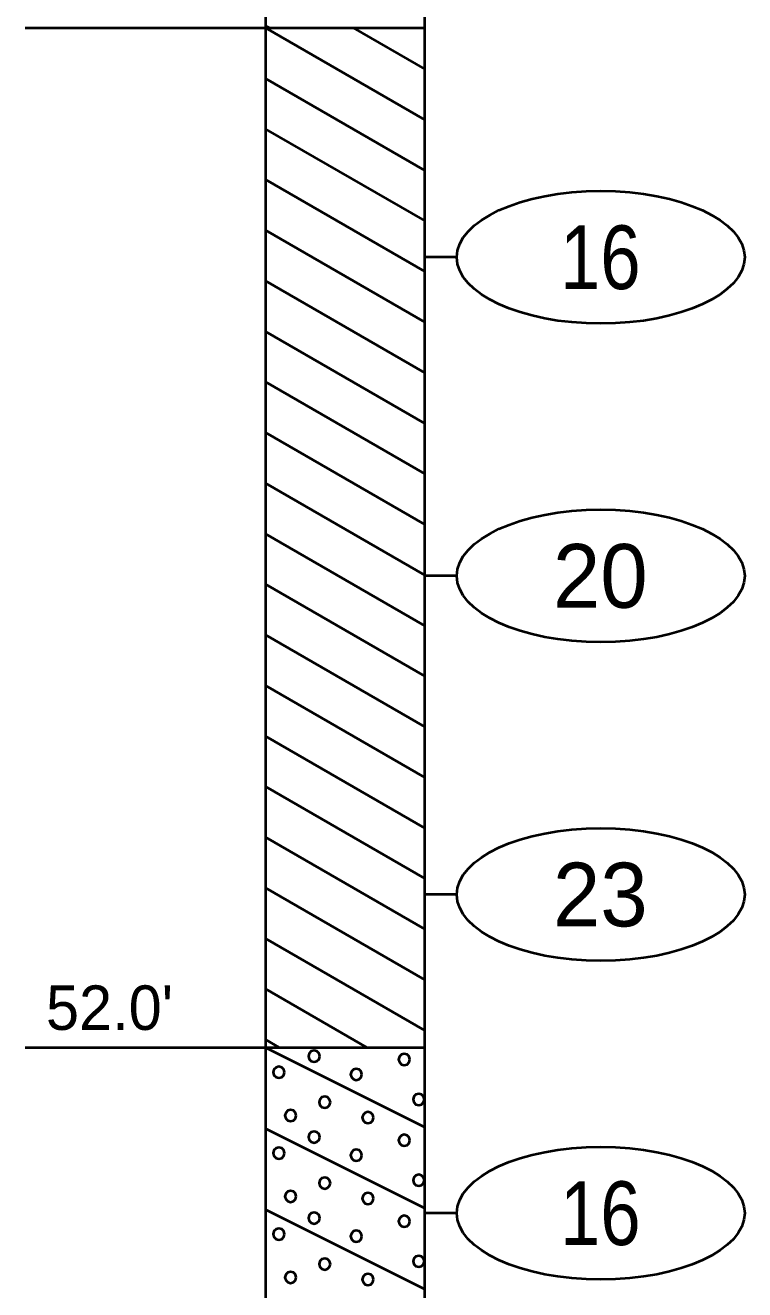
# Model space of a CAD drawing. Extents: x -76 to 974, y -1080 to -735.
# Drawn here: x 37.75 to 49.03, y -820.52 to -800.68 of the extents above; entities that cross this region are included whole.
import ezdxf
from ezdxf.enums import TextEntityAlignment as Align

# ---------------------------------------------------------------- set-up
doc = ezdxf.new("R2010")
doc.units = 0
doc.header["$LTSCALE"] = 0.36
doc.layers.add('27', color=7, linetype='Continuous', lineweight=40)

msp = doc.modelspace()

# ---------------------------------------------------------------- linework, layer by layer
at = {"layer": '27'}
for p, q in [((41.5129, -786.7173), (41.5129, -800.7173)), ((44.0129, -800.7173), (44.0129, -786.7173)), ((37.7455, -800.7173), (41.5129, -800.7173)), ((41.5129, -800.6873), (41.5729, -800.7173)), ((41.5129, -800.7173), (44.0129, -800.7173)), ((41.5129, -800.7173), (44.0129, -802.1607)), ((41.5129, -800.7173), (41.5129, -816.7173)), ((42.8877, -800.7173), (44.0129, -801.3669)), ((42.8877, -800.7173), (44.0129, -801.3669)), ((44.0129, -816.7173), (44.0129, -800.7173)), ((41.5129, -801.511), (44.0129, -802.9544)), ((41.5129, -801.511), (44.0129, -802.9544)), ((41.5129, -802.3048), (44.0129, -803.7482)), ((41.5129, -803.0985), (44.0129, -804.5419)), ((41.5129, -803.0985), (44.0129, -804.5419)), ((41.5129, -803.8923), (44.0129, -805.3357)), ((44.5129, -804.3173), (44.0129, -804.3173)), ((41.5129, -804.686), (44.0129, -806.1294)), ((41.5129, -804.686), (44.0129, -806.1294)), ((41.5129, -805.4798), (44.0129, -806.9232)), ((41.5129, -806.2735), (44.0129, -807.7169)), ((41.5129, -806.2735), (44.0129, -807.7169)), ((41.5129, -807.0673), (44.0129, -808.5107)), ((41.5129, -807.861), (44.0129, -809.3044)), ((41.5129, -807.861), (44.0129, -809.3044)), ((41.5129, -808.6548), (44.0129, -810.0982)), ((41.5129, -809.4485), (44.0129, -810.8919)), ((41.5129, -809.4485), (44.0129, -810.8919)), ((44.5129, -809.3173), (44.0129, -809.3173)), ((41.5129, -810.2423), (44.0129, -811.6857)), ((41.5129, -811.036), (44.0129, -812.4794)), ((41.5129, -811.036), (44.0129, -812.4794)), ((41.5129, -811.8298), (44.0129, -813.2732)), ((41.5129, -812.6235), (44.0129, -814.0669)), ((41.5129, -812.6235), (44.0129, -814.0669)), ((41.5129, -813.4173), (44.0129, -814.8607)), ((41.5129, -814.211), (44.0129, -815.6544)), ((41.5129, -814.211), (44.0129, -815.6544)), ((44.5129, -814.3173), (44.0129, -814.3173)), ((41.5129, -815.0048), (44.0129, -816.4482)), ((41.5129, -815.7985), (43.1042, -816.7173)), ((41.5129, -815.7985), (43.1042, -816.7173)), ((41.5129, -816.5923), (41.7294, -816.7173)), ((37.7455, -816.7173), (41.5129, -816.7173)), ((41.5129, -816.7173), (44.0129, -816.7173)), ((41.5129, -816.7173), (44.0129, -817.9673)), ((41.5129, -816.7173), (41.5129, -821.7173)), ((44.0129, -821.7173), (44.0129, -816.7173)), ((41.5129, -817.9873), (44.0129, -819.2373)), ((41.5129, -819.2573), (44.0129, -820.5073)), ((44.5129, -819.3173), (44.0129, -819.3173))]:
    msp.add_line(p, q, dxfattribs=at)
for points in [[(42.3636, -816.8536), (42.3517, -816.8092), (42.3191, -816.7766), (42.2747, -816.7647), (42.2302, -816.7766), (42.1977, -816.8092), (42.1858, -816.8536), (42.1977, -816.8981), (42.2302, -816.9306), (42.2747, -816.9425), (42.3191, -816.9306), (42.3517, -816.8981)], [(43.7784, -816.9045), (43.7665, -816.8601), (43.734, -816.8275), (43.6895, -816.8156), (43.6451, -816.8275), (43.6126, -816.8601), (43.6006, -816.9045), (43.6126, -816.949), (43.6451, -816.9815), (43.6895, -816.9934), (43.734, -816.9815), (43.7665, -816.949)], [(41.8105, -817.1054), (41.7986, -817.0609), (41.7661, -817.0284), (41.7216, -817.0165), (41.6772, -817.0284), (41.6446, -817.0609), (41.6327, -817.1054), (41.6446, -817.1498), (41.6772, -817.1824), (41.7216, -817.1943), (41.7661, -817.1824), (41.7986, -817.1498)], [(43.0258, -817.1384), (43.0139, -817.094), (42.9814, -817.0615), (42.9369, -817.0495), (42.8925, -817.0615), (42.86, -817.094), (42.848, -817.1384), (42.86, -817.1829), (42.8925, -817.2154), (42.9369, -817.2273), (42.9814, -817.2154), (43.0139, -817.1829)], [(42.5301, -817.5758), (42.5181, -817.5313), (42.4856, -817.4988), (42.4412, -817.4869), (42.3967, -817.4988), (42.3642, -817.5313), (42.3523, -817.5758), (42.3642, -817.6202), (42.3967, -817.6528), (42.4412, -817.6647), (42.4856, -817.6528), (42.5181, -817.6202)], [(44.0047, -817.5325), (43.9928, -817.4881), (43.9603, -817.4555), (43.9158, -817.4436), (43.8714, -817.4555), (43.8388, -817.4881), (43.8269, -817.5325), (43.8388, -817.577), (43.8714, -817.6095), (43.9158, -817.6214), (43.9603, -817.6095), (43.9928, -817.577)], [(41.9948, -817.7843), (41.9829, -817.7398), (41.9504, -817.7073), (41.9059, -817.6954), (41.8615, -817.7073), (41.829, -817.7398), (41.817, -817.7843), (41.829, -817.8287), (41.8615, -817.8612), (41.9059, -817.8732), (41.9504, -817.8612), (41.9829, -817.8287)], [(43.2076, -817.8173), (43.1957, -817.7729), (43.1632, -817.7403), (43.1187, -817.7284), (43.0743, -817.7403), (43.0418, -817.7729), (43.0298, -817.8173), (43.0418, -817.8618), (43.0743, -817.8943), (43.1187, -817.9062), (43.1632, -817.8943), (43.1957, -817.8618)], [(42.3635, -818.1224), (42.3516, -818.078), (42.3191, -818.0454), (42.2746, -818.0335), (42.2302, -818.0454), (42.1976, -818.078), (42.1857, -818.1224), (42.1976, -818.1669), (42.2302, -818.1994), (42.2746, -818.2113), (42.3191, -818.1994), (42.3516, -818.1669)], [(43.7784, -818.1733), (43.7665, -818.1288), (43.734, -818.0963), (43.6895, -818.0844), (43.6451, -818.0963), (43.6126, -818.1288), (43.6006, -818.1733), (43.6126, -818.2177), (43.6451, -818.2502), (43.6895, -818.2622), (43.734, -818.2502), (43.7665, -818.2177)], [(41.8105, -818.3741), (41.7986, -818.3297), (41.7661, -818.2971), (41.7216, -818.2852), (41.6772, -818.2971), (41.6446, -818.3297), (41.6327, -818.3741), (41.6446, -818.4186), (41.6772, -818.4511), (41.7216, -818.463), (41.7661, -818.4511), (41.7986, -818.4186)], [(43.0258, -818.4072), (43.0139, -818.3627), (42.9814, -818.3302), (42.9369, -818.3183), (42.8925, -818.3302), (42.86, -818.3627), (42.848, -818.4072), (42.86, -818.4516), (42.8925, -818.4842), (42.9369, -818.4961), (42.9814, -818.4842), (43.0139, -818.4516)], [(42.5301, -818.8445), (42.5181, -818.8), (42.4856, -818.7675), (42.4412, -818.7556), (42.3967, -818.7675), (42.3642, -818.8), (42.3523, -818.8445), (42.3642, -818.8889), (42.3967, -818.9215), (42.4412, -818.9334), (42.4856, -818.9215), (42.5181, -818.8889)], [(44.0047, -818.8013), (43.9928, -818.7568), (43.9603, -818.7243), (43.9158, -818.7124), (43.8714, -818.7243), (43.8388, -818.7568), (43.8269, -818.8013), (43.8388, -818.8457), (43.8714, -818.8783), (43.9158, -818.8902), (43.9603, -818.8783), (43.9928, -818.8457)], [(41.9948, -819.053), (41.9829, -819.0085), (41.9504, -818.976), (41.9059, -818.9641), (41.8615, -818.976), (41.829, -819.0085), (41.817, -819.053), (41.829, -819.0974), (41.8615, -819.13), (41.9059, -819.1419), (41.9504, -819.13), (41.9829, -819.0974)], [(43.2076, -819.086), (43.1957, -819.0416), (43.1632, -819.009), (43.1187, -818.9971), (43.0743, -819.009), (43.0418, -819.0416), (43.0298, -819.086), (43.0418, -819.1305), (43.0743, -819.163), (43.1187, -819.1749), (43.1632, -819.163), (43.1957, -819.1305)], [(42.3636, -819.3936), (42.3517, -819.3492), (42.3191, -819.3166), (42.2747, -819.3047), (42.2302, -819.3166), (42.1977, -819.3492), (42.1858, -819.3936), (42.1977, -819.4381), (42.2302, -819.4706), (42.2747, -819.4825), (42.3191, -819.4706), (42.3517, -819.4381)], [(43.7784, -819.4445), (43.7665, -819.4001), (43.734, -819.3675), (43.6895, -819.3556), (43.6451, -819.3675), (43.6126, -819.4001), (43.6006, -819.4445), (43.6126, -819.489), (43.6451, -819.5215), (43.6895, -819.5334), (43.734, -819.5215), (43.7665, -819.489)], [(41.8105, -819.6454), (41.7986, -819.6009), (41.7661, -819.5684), (41.7216, -819.5565), (41.6772, -819.5684), (41.6446, -819.6009), (41.6327, -819.6454), (41.6446, -819.6898), (41.6772, -819.7224), (41.7216, -819.7343), (41.7661, -819.7224), (41.7986, -819.6898)], [(43.0258, -819.6784), (43.0139, -819.634), (42.9814, -819.6015), (42.9369, -819.5895), (42.8925, -819.6015), (42.86, -819.634), (42.848, -819.6784), (42.86, -819.7229), (42.8925, -819.7554), (42.9369, -819.7673), (42.9814, -819.7554), (43.0139, -819.7229)], [(44.0047, -820.0725), (43.9928, -820.0281), (43.9603, -819.9955), (43.9158, -819.9836), (43.8714, -819.9955), (43.8388, -820.0281), (43.8269, -820.0725), (43.8388, -820.117), (43.8714, -820.1495), (43.9158, -820.1614), (43.9603, -820.1495), (43.9928, -820.117)], [(42.5301, -820.1158), (42.5181, -820.0713), (42.4856, -820.0388), (42.4412, -820.0269), (42.3967, -820.0388), (42.3642, -820.0713), (42.3523, -820.1158), (42.3642, -820.1602), (42.3967, -820.1928), (42.4412, -820.2047), (42.4856, -820.1928), (42.5181, -820.1602)], [(41.9948, -820.3243), (41.9829, -820.2798), (41.9504, -820.2473), (41.9059, -820.2354), (41.8615, -820.2473), (41.829, -820.2798), (41.817, -820.3243), (41.829, -820.3687), (41.8615, -820.4012), (41.9059, -820.4132), (41.9504, -820.4012), (41.9829, -820.3687)], [(43.2076, -820.3573), (43.1957, -820.3129), (43.1632, -820.2803), (43.1187, -820.2684), (43.0743, -820.2803), (43.0418, -820.3129), (43.0298, -820.3573), (43.0418, -820.4018), (43.0743, -820.4343), (43.1187, -820.4462), (43.1632, -820.4343), (43.1957, -820.4018)]]:
    msp.add_lwpolyline(points, close=True, dxfattribs=at)
for centre in [(46.7703, -804.3173), (46.7703, -809.3173), (46.7703, -814.3173), (46.7703, -819.3173)]:
    msp.add_ellipse(centre, major_axis=(2.2574, 0), ratio=0.461538, dxfattribs=at)

# ---------------------------------------------------------------- texts
at = {"layer": '27', "width": 0.85}
for p in [(46.7631, -804.8172), (46.7631, -819.8172)]:
    msp.add_text('16', height=1, dxfattribs=at).set_placement(p, align=Align.CENTER)
at = {"layer": '27'}
for s, p in [('20', (46.7632, -809.8172)), ('23', (46.7632, -814.8172))]:
    msp.add_text(s, height=1, dxfattribs=at).set_placement(p, align=Align.CENTER)
msp.add_text("52.0'", height=0.6976, dxfattribs=at).set_placement((38.0695, -816.4409))

doc.saveas('drawing.dxf')
